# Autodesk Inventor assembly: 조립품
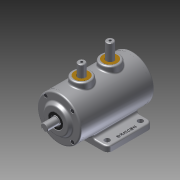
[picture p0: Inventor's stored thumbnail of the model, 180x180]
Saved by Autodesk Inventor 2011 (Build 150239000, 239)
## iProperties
Created: 2014-12
Part Number: 조립품
Document SubType Name: Assembly
Designer: user
Author: user
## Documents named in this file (10)
- C:\Documents and Settings\user\바탕 화면\441225V1016\조립품.iam
- C:\Documents and Settings\user\바탕 화면\441225V1016\슬라이더.ipt
- C:\Documents and Settings\user\바탕 화면\441225V1016\앞커버.ipt
- C:\Documents and Settings\user\바탕 화면\441225V1016\오일실.ipt
- C:\Documents and Settings\user\바탕 화면\441225V1016\M4-소켓머리.ipt
- C:\Documents and Settings\user\바탕 화면\441225V1016\1-본체.ipt
- C:\Documents and Settings\user\바탕 화면\441225V1016\2-축.ipt
- C:\Documents and Settings\user\바탕 화면\441225V1016\뒷커버.ipt
- C:\Documents and Settings\user\바탕 화면\441225V1016\베어링 6203.ipt
- C:\Documents and Settings\user\바탕 화면\441225V1016\부시.ipt
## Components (13 placed, 5 different names)
1. 1-본체:1
2. 8-오일실:1
3. 2-축:1
4. 7-베어링 6203:1
5. 7-베어링 6203:2
6. 9-M4-소켓머리:1
7. 9-M4-소켓머리:2
8. 9-M4-소켓머리:3
9. 9-M4-소켓머리:4
10. 9-M4-소켓머리:5
11. 9-M4-소켓머리:6
12. 9-M4-소켓머리:7
13. 9-M4-소켓머리:8
